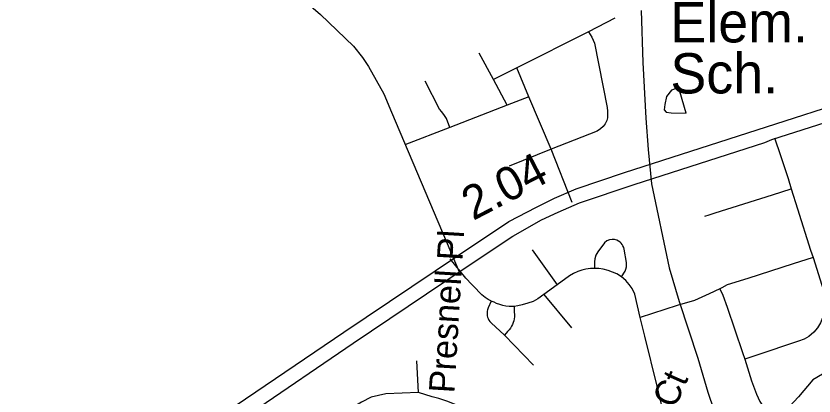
# Model space of a CAD drawing. Extents: x 1383679 to 1536984, y 460658 to 651027.
# Drawn here: x 1408734 to 1411707, y 501053 to 502468 of the extents above; entities that cross this region are included whole.
import ezdxf

# ---------------------------------------------------------------- set-up
doc = ezdxf.new("R2010")
doc.units = 0
for name, color, linetype in [('Exist Cultural Educational Facility Elementary CELL', 7, 'Continuous'), ('Exist Hydrographic Creek Single Shore', 7, 'Continuous'), ('Exist Hydrographic Misc Water Feature', 7, 'Continuous'), ('Exist Road Non-System Type 51', 7, 'Continuous'), ('Exist Road Non-System Type 51 Label', 7, 'Continuous'), ('Exist Road Primary NC Service Mileage Hundredths English Label', 7, 'Continuous'), ('Exist Road Primary NC UnDivided 4 Lane Attributed', 7, 'Continuous')]:
    doc.layers.add(name, color=color, linetype=linetype)

msp = doc.modelspace()

# ---------------------------------------------------------------- linework, layer by layer
at = {"layer": 'Exist Hydrographic Creek Single Shore'}
for points in [[(1411063.7, 502487.9), (1411069.9, 502294.1), (1411080, 502088), (1411089.7, 501971.2), (1411101.1, 501843), (1411167, 501529.8), (1411204.6, 501405.1), (1411274.6, 501193.7), (1411312.1, 501066.6), (1411376.4, 500877.3), (1411399.3, 500822.7)], [(1412794.7, 502398.1), (1412709.4, 502231.6), (1412611.5, 502035.8), (1412567.3, 501916.9), (1412540, 501855), (1412492, 501755.9), (1412386.4, 501570.1), (1412334.6, 501482.5), (1412275.6, 501429.5), (1412180.5, 501375.7), (1412006.6, 501277.4), (1411897.6, 501229.6), (1411790.2, 501163.6), (1411703.2, 501112.8), (1411649.9, 501049.9), (1411598.7, 500995.1), (1411497.1, 500911), (1411442.1, 500862.1), (1411399.3, 500822.7)]]:
    msp.add_lwpolyline(points, dxfattribs=at)
at = {"layer": 'Exist Hydrographic Misc Water Feature'}
msp.add_lwpolyline([(1411230.4, 502106.3), (1411207.9, 502187.1), (1411194.2, 502197.3), (1411175.9, 502191.9), (1411157.6, 502168.5), (1411150.9, 502138.2), (1411148.5, 502118.6), (1411156.3, 502110.2), (1411174.4, 502107.4), (1411230.4, 502106.3)], dxfattribs=at)
at = {"layer": 'Exist Road Non-System Type 51'}
for p, q in [((1410965.4, 502459.2), (1410866.5, 502409.3)), ((1410866.5, 502409.3), (1410600, 502274.8)), ((1410512.9, 502230.8), (1410459.9, 502329.9)), ((1410600, 502274.8), (1410512.9, 502230.8)), ((1410644.1, 502166.6), (1410600, 502274.8)), ((1410563.8, 502135.5), (1410512.9, 502230.8)), ((1410644.1, 502166.6), (1410563.8, 502135.5)), ((1410728.4, 501971.6), (1410644.1, 502166.6)), ((1410563.8, 502135.5), (1410350.4, 502053)), ((1410350.4, 502053), (1410182.9, 501988.2)), ((1410728.4, 501971.6), (1410571.2, 501909.2)), ((1410806.4, 501774), (1410728.4, 501971.6)), ((1410656.6, 501597.2), (1410749.9, 501466.7)), ((1410749.9, 501466.7), (1410700, 501430.7)), ((1410700, 501430.7), (1410804.2, 501307.1)), ((1410553.4, 501279.8), (1410661.6, 501168)), ((1410233.6, 501065.7), (1410226.9, 501184.2))]:
    msp.add_line(p, q, dxfattribs=at)
for points in [[(1406959.6, 504223.3), (1407037.3, 504172.6), (1408317.7, 503410), (1408372.3, 503379.1), (1408441.3, 503342.5), (1408522.5, 503306.6), (1408879.4, 503210.4), (1408921.1, 503197.4), (1408951.9, 503186.9), (1409070.9, 503132.4), (1409159.8, 503076.8), (1409182.8, 503060), (1409210.2, 503037.9), (1409349.6, 502919.9), (1409868.6, 502473.9), (1409990.9, 502356.1), (1410024.8, 502313.2), (1410047, 502279.4), (1410104.6, 502177.8), (1410133.3, 502110.2), (1410384.7, 501515.1)], [(1410866.5, 502409.3), (1410879.1, 502389.2), (1410884.9, 502378.2), (1410888.9, 502366.6), (1410936.8, 502126.8), (1410938.1, 502113.9), (1410938.1, 502101.6), (1410937.4, 502089.2), (1410934.9, 502078.2), (1410929, 502066.6), (1410921.1, 502056.8), (1410911.5, 502047.2), (1410899.1, 502039.3), (1410728.4, 501971.6)], [(1410350.4, 502053), (1410338.4, 502085.6), (1410330.5, 502097.3), (1410320.1, 502110.4), (1410312.2, 502120.8), (1410258.6, 502225.3)], [(1411560.6, 502014.2), (1411582.8, 501948.5), (1411610.6, 501862.4), (1411622.6, 501824.4)], [(1411300.4, 501722.5), (1411316.6, 501727.4), (1411338.6, 501734.8), (1411553.1, 501802.3), (1411622.6, 501824.4)], [(1411622.6, 501824.4), (1411645.9, 501749.8), (1411694.6, 501595.6), (1411703.5, 501568.2)], [(1410990.1, 501496.2), (1411003.2, 501518), (1411006.6, 501525.6), (1411008.4, 501533.4), (1411008.8, 501542.4), (1411008.4, 501550.6), (1410999.4, 501600.1), (1410998.1, 501605.5), (1410995.4, 501612.4), (1410992.8, 501617.2), (1410989.1, 501621.8), (1410984.9, 501626), (1410979.1, 501629.9), (1410972.9, 501633.2), (1410964.1, 501635.3), (1410954.8, 501635.6), (1410945.6, 501634.1), (1410935.8, 501630.2), (1410926.9, 501623.4), (1410901.6, 501590), (1410894.9, 501577.3), (1410891.1, 501563.9), (1410889.6, 501552), (1410889.6, 501528.2)], [(1410503.9, 501406.6), (1410502.8, 501407.1), (1410493.4, 501412.2), (1410482, 501420), (1410470.1, 501429.4), (1410459.9, 501439.3), (1410446.6, 501452.6), (1410431.9, 501468.6), (1410410.5, 501492.1), (1410351.4, 501564)], [(1411703.5, 501568.2), (1411629.9, 501544.8), (1411460.6, 501490.7), (1411383.8, 501467.1), (1411364.1, 501456.2), (1411356.2, 501452.5)], [(1411703.5, 501568.2), (1411736.9, 501465.1), (1411746.2, 501435.7), (1411749.9, 501412.7), (1411750.6, 501391.2), (1411747, 501367.5), (1411739.1, 501343.8), (1411731.9, 501325.9), (1411719.8, 501306.5), (1411706.1, 501290), (1411687.4, 501275), (1411670.9, 501264.9), (1411649.4, 501257.1), (1411490.9, 501204), (1411449, 501189.5)], [(1410889.6, 501528.2), (1410874.1, 501528.2), (1410857.6, 501525.2), (1410842.1, 501521.5), (1410827.1, 501516.3), (1410810.9, 501508.8), (1410795.9, 501499.9), (1410749.9, 501466.7)], [(1410990.1, 501496.2), (1410972.9, 501507.8), (1410956.9, 501514.4), (1410940.2, 501520), (1410921.6, 501525.2), (1410905.4, 501527.5), (1410890.4, 501528.2), (1410889.6, 501528.2)], [(1411059, 501345), (1411039.9, 501431.5), (1411030.2, 501453.1), (1411019.1, 501467.9), (1411005.8, 501482.8), (1410990.1, 501496.2)], [(1411356.2, 501452.5), (1411316.9, 501433.6), (1411261.8, 501409), (1411197.8, 501390.2), (1411059, 501345)], [(1411356.2, 501452.5), (1411368, 501428.7), (1411383.8, 501384.3), (1411440.9, 501215), (1411449, 501189.5)], [(1410700, 501430.7), (1410678.4, 501415.2), (1410661.2, 501405.4), (1410640.4, 501398), (1410620.4, 501392.1), (1410603.8, 501388.1), (1410589.4, 501386.2)], [(1410503.9, 501406.6), (1410493.1, 501381.2), (1410490.1, 501373.9), (1410489.1, 501368.2), (1410488.9, 501363.1), (1410488.9, 501357.3), (1410489.5, 501351.6), (1410491, 501346.2), (1410493.1, 501341.1), (1410496.1, 501335.9), (1410499.4, 501330.8), (1410504.6, 501325.3), (1410553.4, 501279.8)], [(1410589.4, 501386.2), (1410571.5, 501386.2), (1410558.6, 501387.8), (1410547.4, 501390.2), (1410536.5, 501393.2), (1410524.5, 501397.8), (1410514.9, 501401.7), (1410503.9, 501406.6)], [(1410589.4, 501386.2), (1410590.2, 501366.1), (1410590.9, 501355.5), (1410590.9, 501347.3), (1410589.9, 501339.8), (1410589, 501332.6), (1410586.6, 501326), (1410584.1, 501319.7), (1410580.6, 501313), (1410576, 501306.1), (1410570.9, 501299.8), (1410565.1, 501293.1), (1410553.4, 501279.8)], [(1411181.6, 500950.3), (1411172.2, 500958), (1411155.1, 500975.2), (1411144.9, 500995.8), (1411123.4, 501089.2), (1411077.1, 501275.9), (1411059, 501345)], [(1411449, 501189.5), (1411474.4, 501109.7), (1411493.1, 501059.5), (1411505.9, 501031.9), (1411524.6, 501003.4), (1411545.2, 500982.8), (1411569.9, 500963), (1411597.4, 500946.2), (1411623, 500935.4), (1411652.5, 500928.6), (1411683.1, 500925.6), (1411711.6, 500925.6), (1411740.1, 500930.5), (1411773.6, 500941.3), (1411798.2, 500953.2), (1411826.8, 500970.9), (1411848.4, 500978.8), (1411873.1, 500981.8)], [(1410233.6, 501065.7), (1410111.4, 501060.9), (1410056.9, 501048), (1410020.6, 501030.4), (1409987.6, 501009.6), (1409957.9, 500985.6), (1409934.8, 500952), (1409915, 500921.5), (1409903.4, 500889.5), (1409900.1, 500857.5), (1409895.2, 500793.4)], [(1410481.2, 500812.6), (1410476.2, 500878.3), (1410454.7, 500935.9), (1410430, 500972.8), (1410406.9, 500995.2), (1410380.5, 501017.6), (1410339.2, 501033.6), (1410309.5, 501043.2), (1410284.7, 501049.6), (1410233.6, 501065.7)]]:
    msp.add_lwpolyline(points, dxfattribs=at)
at = {"layer": 'Exist Road Primary NC UnDivided 4 Lane Attributed'}
for points in [[(1408282.2, 500133.7), (1408851.4, 500541), (1409092.2, 500704.4), (1409091.4, 500706), (1409350.8, 500881.8), (1409554.4, 501019), (1409955.2, 501290.9), (1410378.7, 501574.4), (1410570, 501703), (1410673, 501756.5), (1410740.3, 501789.8), (1410820.8, 501823.9), (1411000.5, 501885.1), (1411529.8, 502054.9), (1411847.2, 502157), (1412098.9, 502238.4), (1412527.8, 502378.6), (1412640.1, 502416.6), (1412816.7, 502485.5)], [(1408403.8, 500155.9), (1408884.7, 500498.3), (1409084.4, 500636.2), (1409386.4, 500840.8), (1409611, 500991.1), (1409990, 501249.1), (1410400.4, 501525.6), (1410584.7, 501648), (1410691.5, 501708.5), (1410754.3, 501737.1), (1410834, 501772), (1411036.9, 501840.9), (1411523.5, 501997.4), (1411550.5, 502007.4), (1412095.8, 502181.8), (1412152.3, 502198.1), (1412546.4, 502328.2), (1412648.6, 502363.1), (1412824.4, 502429.7), (1412995.1, 502497.1)]]:
    msp.add_lwpolyline(points, dxfattribs=at)

# ---------------------------------------------------------------- texts
at = {"layer": 'Exist Cultural Educational Facility Elementary CELL'}
for s, p in [('Elem. ', (1411172.1, 502369.4)), ('Sch.', (1411172.1, 502179.4))]:
    msp.add_text(s, height=150, dxfattribs=at).set_placement(p)
at = {"layer": 'Exist Road Non-System Type 51 Label'}
for s, rotation, p in [('Presnell Pl', 86.5313, (1410366.9, 501061.8)), ('Woffington Ct', 66.0531, (1410927.8, 500415.6))]:
    msp.add_text(s, height=95, rotation=rotation, dxfattribs=at).set_placement(p)
at = {"layer": 'Exist Road Primary NC Service Mileage Hundredths English Label'}
msp.add_text('2.04', height=125, rotation=27.4321, dxfattribs=at).set_placement((1410436.9, 501704.4))

doc.saveas('drawing.dxf')
